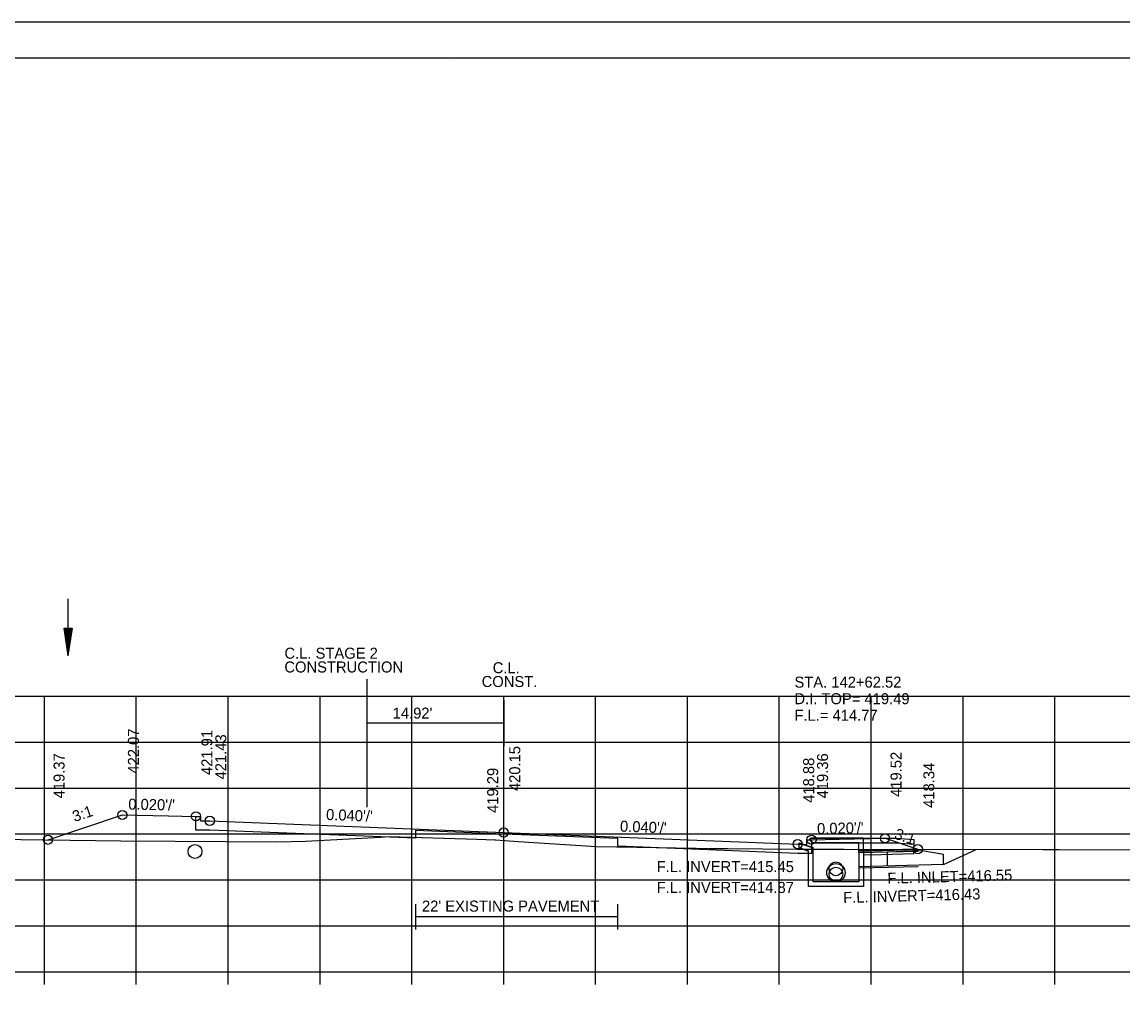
# Model space of a CAD drawing. Extents: x 1538688 to 1540766, y 656250 to 671912.
# Drawn here: x 1538805.7 to 1538925.6, y 662632.6 to 662738 of the extents above; entities that cross this region are included whole.
import ezdxf

# ---------------------------------------------------------------- set-up
doc = ezdxf.new("R2010")
doc.units = 0
for name, color, linetype in [('15', 7, 'Continuous'), ('18', 7, 'Continuous'), ('20', 7, 'Continuous'), ('22', 7, 'Continuous'), ('26', 7, 'Continuous'), ('39', 7, 'Continuous'), ('40', 7, 'Continuous'), ('41', 7, 'Continuous'), ('42', 7, 'Continuous'), ('7', 7, 'Continuous'), ('Borings', 7, 'Continuous'), ('Default', 7, 'Continuous'), ('RipRap', 7, 'Continuous'), ('Wall Heights', 7, 'Continuous')]:
    doc.layers.add(name, color=color, linetype=linetype)

msp = doc.modelspace()

# ---------------------------------------------------------------- linework, layer by layer
at = {"layer": '15'}
for p, q in [((1538810.29, 662672.07), (1538810.74, 662669.07)), ((1538810.29, 662672.07), (1538811.19, 662672.07)), ((1538810.36, 662672.07), (1538810.74, 662669.57)), ((1538810.44, 662672.07), (1538810.74, 662670.09)), ((1538810.51, 662672.07), (1538810.74, 662670.59)), ((1538810.59, 662672.07), (1538810.74, 662671.1)), ((1538810.67, 662672.07), (1538810.74, 662671.6)), ((1538811.19, 662672.07), (1538810.74, 662669.07)), ((1538810.88, 662672.07), (1538810.74, 662671.1)), ((1538811.04, 662672.07), (1538810.74, 662670.09)), ((1538811.11, 662672.07), (1538810.74, 662669.57)), ((1538810.96, 662672.07), (1538810.74, 662670.59)), ((1538810.81, 662672.07), (1538810.74, 662671.6))]:
    msp.add_line(p, q, dxfattribs=at)
at = {"layer": '18'}
msp.add_lwpolyline([(1538802.98, 662649.12), (1538808.24, 662649.05), (1538816.49, 662648.93), (1538822.42, 662648.88), (1538833.48, 662648.81), (1538836.61, 662648.88), (1538844.78, 662649.34), (1538845.71, 662649.42), (1538855.24, 662649.11), (1538857.2, 662649.03), (1538857.31, 662649.03), (1538859.75, 662648.87), (1538868.29, 662648.31), (1538879.12, 662648.12), (1538880.56, 662648.09), (1538882.59, 662648.08), (1538890.12, 662648.03), (1538894.33, 662648.03), (1538895.23, 662648.03), (1538916.88, 662647.99), (1538918.63, 662647.98), (1538929.71, 662647.97)], dxfattribs=at)
at = {"layer": '20'}
msp.add_lwpolyline([(1538808.57, 662649.05), (1538816.67, 662651.75), (1538821.67, 662651.65), (1538824.67, 662651.59), (1538825.17, 662651.59), (1538825.18, 662651.09), (1538826.18, 662651.11), (1538858.18, 662649.84), (1538890.18, 662648.57), (1538891.18, 662648.55), (1538891.19, 662649.05), (1538891.69, 662649.05), (1538894.69, 662649.11), (1538899.69, 662649.21), (1538903.26, 662648.02)], dxfattribs=at)
at = {"layer": '22'}
for p, q in [((1538718.18, 662664.68), (1538998.18, 662664.68)), ((1538808.18, 662634.68), (1538808.18, 662664.68)), ((1538818.18, 662634.68), (1538818.18, 662664.68)), ((1538828.18, 662634.68), (1538828.18, 662664.68)), ((1538838.18, 662634.68), (1538838.18, 662664.68)), ((1538848.18, 662634.68), (1538848.18, 662664.68)), ((1538858.18, 662634.68), (1538858.18, 662664.68)), ((1538868.18, 662634.68), (1538868.18, 662664.68)), ((1538878.18, 662634.68), (1538878.18, 662664.68)), ((1538888.18, 662634.68), (1538888.18, 662664.68)), ((1538898.18, 662634.68), (1538898.18, 662664.68)), ((1538908.18, 662634.68), (1538908.18, 662664.68)), ((1538918.18, 662634.68), (1538918.18, 662664.68)), ((1538718.18, 662659.68), (1538998.18, 662659.68)), ((1538718.18, 662654.68), (1538998.18, 662654.68)), ((1538718.18, 662649.68), (1538998.18, 662649.68)), ((1538718.18, 662644.68), (1538998.18, 662644.68)), ((1538718.18, 662639.68), (1538998.18, 662639.68)), ((1538718.18, 662634.68), (1538998.18, 662634.68))]:
    msp.add_line(p, q, dxfattribs=at)
at = {"layer": '26'}
for p, q in [((1538687.78, 662738.04), (1539021.11, 662738.04)), ((1538900.83, 662649.21), (1538902.86, 662649.06)), ((1538900.86, 662648.71), (1538902.85, 662648.56)), ((1538903.28, 662647.95), (1538896.85, 662647.78)), ((1538903.28, 662646.12), (1538896.85, 662645.94))]:
    msp.add_line(p, q, dxfattribs=at)
msp.add_lwpolyline([(1538687.77, 662738.04), (1539021.11, 662738.04), (1539021.11, 662524.7), (1538687.77, 662524.7)], close=True, dxfattribs=at)
for points in [[(1538896.85, 662648.71), (1538899.35, 662648.71), (1538900.86, 662648.71)], [(1538897.35, 662649.21), (1538899.35, 662649.21), (1538900.86, 662649.21)], [(1538897.37, 662647.39), (1538899.29, 662647.45), (1538902.84, 662647.56), (1538902.86, 662649.06)], [(1538896.85, 662647.87), (1538899.27, 662647.95), (1538902.82, 662648.06)]]:
    msp.add_lwpolyline(points, dxfattribs=at)
for centre in [(1538816.67, 662651.75), (1538824.67, 662651.59), (1538826.18, 662651.11), (1538858.18, 662649.84), (1538808.57, 662649.05), (1538890.18, 662648.57), (1538891.69, 662649.05), (1538899.69, 662649.21), (1538903.26, 662648.02)]:
    msp.add_circle(centre, 0.5, dxfattribs=at)
at = {"layer": '39'}
for p, q in [((1538810.74, 662675.26), (1538810.74, 662669.07)), ((1538890.35, 662648.73), (1538891.85, 662648.21)), ((1538890.35, 662648.69), (1538891.85, 662648.17)), ((1538891.51, 662649.05), (1538891.6, 662649.21)), ((1538891.51, 662649), (1538891.6, 662649.17)), ((1538891.51, 662649.05), (1538891.85, 662648.71)), ((1538891.51, 662649), (1538891.85, 662648.67)), ((1538897.35, 662649.21), (1538891.6, 662649.21)), ((1538897.35, 662649.17), (1538891.6, 662649.17)), ((1538896.85, 662648.71), (1538891.85, 662648.71)), ((1538896.85, 662648.67), (1538891.85, 662648.67)), ((1538896.85, 662647.67), (1538896.85, 662648.67)), ((1538897.35, 662647.67), (1538897.35, 662649.17)), ((1538890.35, 662648.2), (1538891.35, 662647.86)), ((1538890.35, 662648.16), (1538891.35, 662647.81)), ((1538891.35, 662647.71), (1538891.35, 662647.86)), ((1538891.35, 662647.67), (1538891.35, 662647.81)), ((1538891.85, 662647.71), (1538891.85, 662648.21)), ((1538891.85, 662647.67), (1538891.85, 662648.17)), ((1538903.28, 662647.78), (1538896.85, 662647.61)), ((1538906.05, 662646.36), (1538909.53, 662647.97)), ((1538906.05, 662646.36), (1538896.85, 662646.11))]:
    msp.add_line(p, q, dxfattribs=at)
for points in [[(1538890.35, 662648.2), (1538890.35, 662648.73)], [(1538890.35, 662648.16), (1538890.35, 662648.69)], [(1538897.35, 662647.67), (1538897.35, 662643.96), (1538894.35, 662643.96), (1538891.35, 662643.96), (1538891.35, 662647.67)], [(1538896.85, 662647.67), (1538896.85, 662644.46), (1538894.35, 662644.46), (1538891.85, 662644.46), (1538891.85, 662647.67)], [(1538906.04, 662646.43), (1538906.05, 662647.43), (1538903.74, 662647.84), (1538899.91, 662647.69), (1538899.91, 662646.19)]]:
    msp.add_lwpolyline(points, dxfattribs=at)
for centre, radius in [((1538824.57, 662647.77), 0.75), ((1538894.35, 662645.46), 1), ((1538894.35, 662645.89), 0.75), ((1538894.35, 662645.3), 0.75)]:
    msp.add_circle(centre, radius, dxfattribs=at)
at = {"layer": '7'}
for p, q in [((1538848.58, 662642.04), (1538848.58, 662639.3)), ((1538870.58, 662642.04), (1538870.58, 662639.3)), ((1538870.58, 662640.67), (1538848.58, 662640.67))]:
    msp.add_line(p, q, dxfattribs=at)
at = {"layer": 'Borings'}
for p, q in [((1538718.18, 662634.68), (1538998.18, 662634.68)), ((1538808.18, 662633.28), (1538808.18, 662634.68)), ((1538818.18, 662633.28), (1538818.18, 662634.68)), ((1538828.18, 662633.28), (1538828.18, 662634.68)), ((1538838.18, 662633.28), (1538838.18, 662634.68)), ((1538848.18, 662633.28), (1538848.18, 662634.68)), ((1538858.18, 662633.28), (1538858.18, 662634.68)), ((1538868.18, 662633.28), (1538868.18, 662634.68)), ((1538878.18, 662633.28), (1538878.18, 662634.68)), ((1538888.18, 662633.28), (1538888.18, 662634.68)), ((1538898.18, 662633.28), (1538898.18, 662634.68)), ((1538908.18, 662633.28), (1538908.18, 662634.68)), ((1538918.18, 662633.28), (1538918.18, 662634.68))]:
    msp.add_line(p, q, dxfattribs=at)
at = {"layer": 'Default'}
for p, q in [((1538843.26, 662666.52), (1538843.26, 662652.61)), ((1538858.18, 662664.23), (1538858.18, 662659.23)), ((1538858.18, 662661.73), (1538843.26, 662661.73))]:
    msp.add_line(p, q, dxfattribs=at)
at = {"layer": 'RipRap'}
for p, q in [((1538700.18, 662734.14), (1539016.36, 662734.14)), ((1538852.7, 662733.88), (1538852.7, 662733.88)), ((1538852.7, 662733.88), (1538852.7, 662733.88))]:
    msp.add_line(p, q, dxfattribs=at)
at = {"layer": 'Wall Heights'}
msp.add_lwpolyline([(1538891.69, 662649.05), (1538891.69, 662647.55), (1538890.18, 662647.57), (1538870.59, 662648.35), (1538870.59, 662649.18), (1538858.18, 662649.67), (1538848.59, 662650.05), (1538848.59, 662649.22), (1538826.18, 662650.11), (1538824.67, 662650.09), (1538824.67, 662651.59)], dxfattribs=at)

# ---------------------------------------------------------------- texts
at = {"layer": '40'}
for s, p in [('STA. 142+62.52', (1538889.83, 662665.6)), ('D.I. TOP= 419.49', (1538889.83, 662663.8)), ('F.L.= 414.77', (1538889.83, 662662)), ('F.L. INVERT=415.45', (1538874.83, 662645.53)), ('F.L. INVERT=414.87', (1538874.83, 662643.26))]:
    msp.add_text(s, height=1.2, dxfattribs=at).set_placement(p)
for s, p in [('F.L. INLET=416.55', (1538899.96, 662644.26)), ('F.L. INVERT=416.43', (1538895.15, 662642.16))]:
    msp.add_text(s, height=1.2, rotation=1.5477, dxfattribs=at).set_placement(p)
at = {"layer": '41'}
for s, p in [('422.07', (1538818.47, 662656.25)), ('421.91', (1538826.47, 662656.09)), ('421.43', (1538827.98, 662655.61)), ('419.37', (1538810.37, 662653.55)), ('420.15', (1538859.98, 662654.34)), ('419.36', (1538893.49, 662653.55)), ('419.52', (1538901.49, 662653.71)), ('418.88', (1538891.98, 662653.07)), ('418.34', (1538905.06, 662652.52)), ('419.29', (1538857.58, 662651.97))]:
    msp.add_text(s, height=1.2, rotation=90, dxfattribs=at).set_placement(p)
at = {"layer": '42'}
for s, rotation, p in [("0.020'/'", 358.8542, (1538817.3, 662652.33)), ('3:1', 18.4349, (1538811.46, 662650.97)), ("0.040'/'", 357.727, (1538838.82, 662651.21)), ("0.040'/'", 357.727, (1538870.82, 662649.94)), ("0.020'/'", 1.1458, (1538892.3, 662649.66)), ('3:1', 341.5651, (1538900.63, 662649.19))]:
    msp.add_text(s, height=1.2, rotation=rotation, dxfattribs=at).set_placement(p)
at = {"layer": '7'}
msp.add_text("22' EXISTING PAVEMENT", height=1.2, dxfattribs=at).set_placement((1538849.28, 662641.23))
at = {"layer": 'Default'}
for s, p in [('C.L. STAGE 2', (1538834.31, 662668.75)), ('CONSTRUCTION', (1538834.3, 662667.25)), ('C.L.', (1538856.98, 662667.17)), ('CONST.', (1538855.78, 662665.67)), ("14.92'", (1538846.09, 662662.23))]:
    msp.add_text(s, height=1.2, dxfattribs=at).set_placement(p)

doc.saveas('drawing.dxf')
